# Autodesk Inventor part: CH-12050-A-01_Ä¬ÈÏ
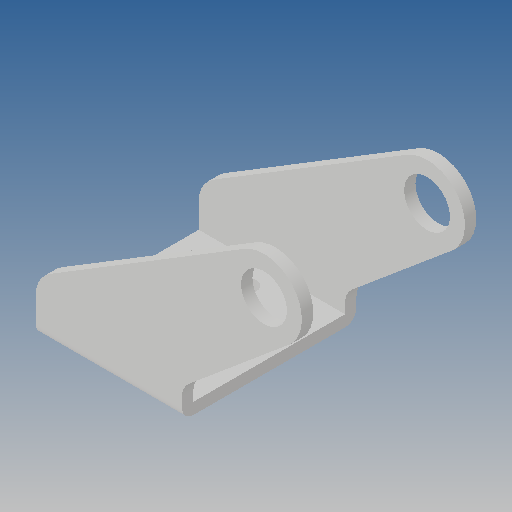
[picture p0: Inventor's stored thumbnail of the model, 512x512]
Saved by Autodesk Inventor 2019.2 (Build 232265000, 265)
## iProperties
Created: 2010-06
Part Number: CH-12050-A-01_Ä¬ÈÏ
Material: Ogólny
Document SubType Name: Modeling
Designer: CADENGINEERING4
Density: 1 g/cm^3
Appearance: Domyślna
Author: CADENGINEERING4
Revision Number: ÈÎºÎ
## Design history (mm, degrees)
feature "NONE"
node "Bryła1"
